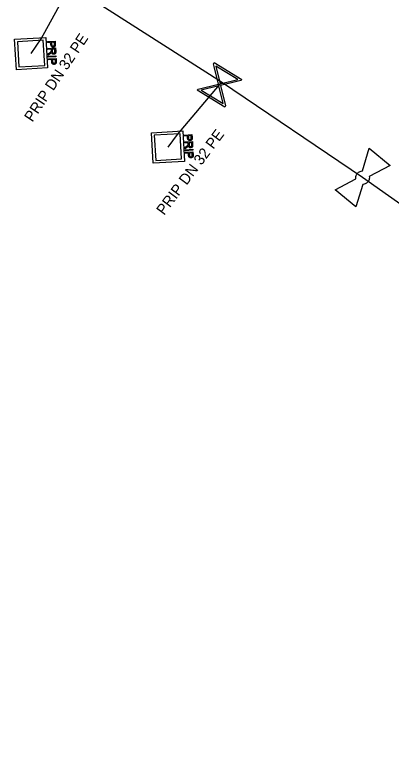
# Model space of a CAD drawing. Extents: x -643544 to -637295, y -1119190 to -1111715.
# Drawn here: x -642015.17 to -641997.66, y -1113502.17 to -1113468.24 of the extents above; entities that cross this region are included whole.
import ezdxf

# ---------------------------------------------------------------- set-up
doc = ezdxf.new("R2010")
doc.units = 0
for name, color, linetype in [('Default', 7, 'Continuous'), ('VP Lomový bod', 7, 'Continuous'), ('VP Popis přípojky', 7, 'Continuous'), ('VP Přípojka', 7, 'Continuous'), ('VP Řad', 7, 'Continuous'), ('VP Šachta', 7, 'Continuous'), ('VP Šoupě', 7, 'Continuous')]:
    doc.layers.add(name, color=color, linetype=linetype)

msp = doc.modelspace()

# ---------------------------------------------------------------- linework, layer by layer
at = {"layer": 'Default'}
for points in [[(-642013.279, -1113469.604), (-642013.277, -1113469.64), (-642013.28, -1113469.659), (-642013.283, -1113469.685), (-642013.294, -1113469.704), (-642013.305, -1113469.723), (-642013.326, -1113469.735), (-642013.348, -1113469.746), (-642013.375, -1113469.748), (-642013.421, -1113469.751), (-642013.454, -1113469.724), (-642013.486, -1113469.697), (-642013.491, -1113469.621)], [(-642013.449, -1113469.619), (-642013.447, -1113469.665), (-642013.429, -1113469.683), (-642013.41, -1113469.701), (-642013.379, -1113469.699), (-642013.357, -1113469.698), (-642013.342, -1113469.686), (-642013.326, -1113469.674), (-642013.323, -1113469.656), (-642013.32, -1113469.643), (-642013.322, -1113469.61)], [(-642013.54, -1113470.014), (-642013.508, -1113469.992), (-642013.492, -1113469.977), (-642013.476, -1113469.963), (-642013.47, -1113469.952), (-642013.464, -1113469.94), (-642013.462, -1113469.929), (-642013.46, -1113469.922), (-642013.461, -1113469.903)], [(-642013.259, -1113469.948), (-642013.256, -1113469.995), (-642013.265, -1113470.021), (-642013.273, -1113470.046), (-642013.296, -1113470.063), (-642013.32, -1113470.079), (-642013.349, -1113470.08), (-642013.388, -1113470.083), (-642013.415, -1113470.06), (-642013.442, -1113470.037), (-642013.452, -1113469.986), (-642013.461, -1113470.005), (-642013.469, -1113470.015), (-642013.486, -1113470.037), (-642013.514, -1113470.057)], [(-642013.418, -1113469.947), (-642013.416, -1113469.98), (-642013.408, -1113469.998), (-642013.401, -1113470.016), (-642013.385, -1113470.024), (-642013.37, -1113470.033), (-642013.352, -1113470.032), (-642013.328, -1113470.03), (-642013.312, -1113470.011), (-642013.297, -1113469.992), (-642013.299, -1113469.951)], [(-642013.234, -1113470.405), (-642013.231, -1113470.44), (-642013.234, -1113470.46), (-642013.237, -1113470.486), (-642013.248, -1113470.505), (-642013.26, -1113470.524), (-642013.281, -1113470.535), (-642013.302, -1113470.547), (-642013.329, -1113470.549), (-642013.375, -1113470.551), (-642013.408, -1113470.525), (-642013.441, -1113470.498), (-642013.445, -1113470.422)], [(-642013.404, -1113470.42), (-642013.401, -1113470.466), (-642013.383, -1113470.484), (-642013.365, -1113470.502), (-642013.333, -1113470.5), (-642013.311, -1113470.499), (-642013.296, -1113470.487), (-642013.281, -1113470.475), (-642013.277, -1113470.456), (-642013.274, -1113470.444), (-642013.276, -1113470.411)], [(-642006.919, -1113473.944), (-642006.917, -1113473.98), (-642006.92, -1113473.999), (-642006.923, -1113474.025), (-642006.934, -1113474.044), (-642006.945, -1113474.063), (-642006.966, -1113474.075), (-642006.988, -1113474.086), (-642007.015, -1113474.088), (-642007.061, -1113474.091), (-642007.094, -1113474.064), (-642007.126, -1113474.037), (-642007.131, -1113473.961)], [(-642007.089, -1113473.959), (-642007.087, -1113474.005), (-642007.069, -1113474.023), (-642007.05, -1113474.041), (-642007.019, -1113474.039), (-642006.997, -1113474.038), (-642006.982, -1113474.026), (-642006.966, -1113474.014), (-642006.963, -1113473.996), (-642006.96, -1113473.983), (-642006.962, -1113473.95)], [(-642007.18, -1113474.354), (-642007.148, -1113474.332), (-642007.132, -1113474.317), (-642007.116, -1113474.303), (-642007.11, -1113474.292), (-642007.104, -1113474.28), (-642007.102, -1113474.269), (-642007.1, -1113474.262), (-642007.101, -1113474.243)], [(-642006.899, -1113474.288), (-642006.896, -1113474.335), (-642006.905, -1113474.361), (-642006.913, -1113474.386), (-642006.936, -1113474.403), (-642006.96, -1113474.419), (-642006.989, -1113474.42), (-642007.028, -1113474.423), (-642007.055, -1113474.4), (-642007.082, -1113474.377), (-642007.092, -1113474.326), (-642007.101, -1113474.345), (-642007.109, -1113474.355), (-642007.126, -1113474.377), (-642007.154, -1113474.397)], [(-642007.058, -1113474.287), (-642007.056, -1113474.32), (-642007.048, -1113474.338), (-642007.041, -1113474.356), (-642007.025, -1113474.364), (-642007.01, -1113474.373), (-642006.992, -1113474.372), (-642006.968, -1113474.37), (-642006.952, -1113474.351), (-642006.937, -1113474.332), (-642006.939, -1113474.291)], [(-642006.874, -1113474.745), (-642006.871, -1113474.78), (-642006.874, -1113474.8), (-642006.877, -1113474.826), (-642006.888, -1113474.845), (-642006.9, -1113474.864), (-642006.921, -1113474.875), (-642006.942, -1113474.887), (-642006.969, -1113474.889), (-642007.015, -1113474.891), (-642007.048, -1113474.865), (-642007.081, -1113474.838), (-642007.085, -1113474.762)], [(-642007.044, -1113474.76), (-642007.041, -1113474.806), (-642007.023, -1113474.824), (-642007.005, -1113474.842), (-642006.973, -1113474.84), (-642006.951, -1113474.839), (-642006.936, -1113474.827), (-642006.921, -1113474.815), (-642006.917, -1113474.796), (-642006.914, -1113474.784), (-642006.916, -1113474.751)], [(-641999.308, -1113475.863), (-641999.317, -1113475.811), (-641999.308, -1113475.757), (-641999.293, -1113475.674), (-641999.241, -1113475.611), (-641999.189, -1113475.548), (-641999.108, -1113475.517), (-641999.059, -1113475.497), (-641999.006, -1113475.497)], [(-641998.69, -1113475.757), (-641998.682, -1113475.808), (-641998.691, -1113475.861), (-641998.707, -1113475.946), (-641998.759, -1113476.009), (-641998.811, -1113476.072), (-641998.889, -1113476.102), (-641998.94, -1113476.122), (-641998.993, -1113476.122)]]:
    msp.add_open_spline(points, degree=3, dxfattribs=at)
at = {"layer": 'VP Lomový bod'}
for points in [[(-641999.006, -1113475.497), (-641998.688, -1113474.448)], [(-641998.688, -1113474.448), (-641997.723, -1113475.243), (-641998.69, -1113475.757)], [(-641998.993, -1113476.122), (-641999.312, -1113477.172), (-642000.277, -1113476.377), (-641999.308, -1113475.863)]]:
    msp.add_lwpolyline(points, dxfattribs=at)
at = {"layer": 'VP Přípojka'}
for points in [[(-642014.4, -1113470.05), (-642013.94, -1113469.36), (-642012.65, -1113467.01), (-642012.57, -1113466.89)], [(-642008.04, -1113474.39), (-642007.6, -1113473.8), (-642005.65, -1113471.5), (-642005.56, -1113471.37)]]:
    msp.add_lwpolyline(points, dxfattribs=at)
at = {"layer": 'VP Řad'}
msp.add_lwpolyline([(-641959.57, -1113502.17), (-641977.07, -1113490.44), (-641983.86, -1113486.1), (-641986.12, -1113484.64), (-641991.34, -1113481.2), (-641999, -1113475.81), (-642005.56, -1113471.37), (-642012.57, -1113466.89)], dxfattribs=at)
at = {"layer": 'VP Šachta'}
for points in [[(-642013.637, -1113470.713), (-642015.086, -1113470.798), (-642015.169, -1113469.387), (-642013.72, -1113469.302), (-642013.637, -1113470.713)], [(-642013.836, -1113469.43), (-642015.039, -1113469.5), (-642014.97, -1113470.67), (-642013.767, -1113470.6), (-642013.836, -1113469.43)], [(-642013.645, -1113469.491), (-642013.287, -1113469.47), (-642013.279, -1113469.604)], [(-642013.491, -1113469.621), (-642013.496, -1113469.529), (-642013.642, -1113469.537), (-642013.645, -1113469.491)], [(-642013.627, -1113469.81), (-642013.268, -1113469.789), (-642013.259, -1113469.948)], [(-642013.461, -1113469.903), (-642013.464, -1113469.849), (-642013.624, -1113469.858), (-642013.627, -1113469.81)], [(-642013.322, -1113469.61), (-642013.327, -1113469.519), (-642013.455, -1113469.526)], [(-642013.455, -1113469.526), (-642013.449, -1113469.619)], [(-642013.514, -1113470.057), (-642013.608, -1113470.125), (-642013.612, -1113470.065), (-642013.54, -1113470.014)], [(-642013.607, -1113470.174), (-642013.248, -1113470.153), (-642013.246, -1113470.199), (-642013.604, -1113470.22), (-642013.607, -1113470.174)], [(-642013.299, -1113469.951), (-642013.306, -1113469.839), (-642013.424, -1113469.846)], [(-642013.424, -1113469.846), (-642013.418, -1113469.947)], [(-642013.6, -1113470.292), (-642013.241, -1113470.271), (-642013.234, -1113470.405)], [(-642013.445, -1113470.422), (-642013.451, -1113470.33), (-642013.597, -1113470.338), (-642013.6, -1113470.292)], [(-642013.276, -1113470.411), (-642013.281, -1113470.32), (-642013.409, -1113470.327)], [(-642013.409, -1113470.327), (-642013.404, -1113470.42)], [(-642007.277, -1113475.053), (-642008.726, -1113475.138), (-642008.809, -1113473.727), (-642007.36, -1113473.642), (-642007.277, -1113475.053)], [(-642007.476, -1113473.77), (-642008.679, -1113473.84), (-642008.61, -1113475.01), (-642007.407, -1113474.94), (-642007.476, -1113473.77)], [(-642007.285, -1113473.831), (-642006.927, -1113473.81), (-642006.919, -1113473.944)], [(-642007.131, -1113473.961), (-642007.136, -1113473.869), (-642007.282, -1113473.877), (-642007.285, -1113473.831)], [(-642006.962, -1113473.95), (-642006.967, -1113473.859), (-642007.095, -1113473.866)], [(-642007.095, -1113473.866), (-642007.089, -1113473.959)], [(-642007.267, -1113474.15), (-642006.908, -1113474.129), (-642006.899, -1113474.288)], [(-642007.101, -1113474.243), (-642007.104, -1113474.189), (-642007.264, -1113474.198), (-642007.267, -1113474.15)], [(-642006.939, -1113474.291), (-642006.946, -1113474.179), (-642007.064, -1113474.186)], [(-642007.064, -1113474.186), (-642007.058, -1113474.287)], [(-642007.154, -1113474.397), (-642007.248, -1113474.465), (-642007.252, -1113474.405), (-642007.18, -1113474.354)], [(-642007.247, -1113474.514), (-642006.888, -1113474.493), (-642006.886, -1113474.539), (-642007.244, -1113474.56), (-642007.247, -1113474.514)], [(-642007.24, -1113474.632), (-642006.881, -1113474.611), (-642006.874, -1113474.745)], [(-642007.085, -1113474.762), (-642007.091, -1113474.67), (-642007.237, -1113474.678), (-642007.24, -1113474.632)], [(-642006.916, -1113474.751), (-642006.921, -1113474.66), (-642007.049, -1113474.667)], [(-642007.049, -1113474.667), (-642007.044, -1113474.76)]]:
    msp.add_lwpolyline(points, dxfattribs=at)
at = {"layer": 'VP Šoupě'}
for points in [[(-642005.901, -1113470.469), (-642004.619, -1113471.249), (-642004.654, -1113471.305), (-642004.779, -1113471.332), (-642005.595, -1113471.531), (-642005.365, -1113472.474), (-642005.399, -1113472.531), (-642006.681, -1113471.751), (-642006.646, -1113471.695), (-642005.702, -1113471.467), (-642005.901, -1113470.651), (-642005.935, -1113470.526), (-642005.901, -1113470.469)], [(-642005.815, -1113470.631), (-642005.616, -1113471.446), (-642004.803, -1113471.247), (-642005.815, -1113470.631)], [(-642005.481, -1113472.371), (-642005.681, -1113471.552), (-642006.498, -1113471.752), (-642005.481, -1113472.371)]]:
    msp.add_lwpolyline(points, dxfattribs=at)

# ---------------------------------------------------------------- texts
at = {"layer": 'VP Popis přípojky'}
for rotation, p in [(56.3099, (-642014.343, -1113473.261)), (53.2858, (-642008.224, -1113477.589))]:
    msp.add_text('PRIP DN 32 PE', height=0.5, rotation=rotation, dxfattribs=at).set_placement(p)

doc.saveas('drawing.dxf')
